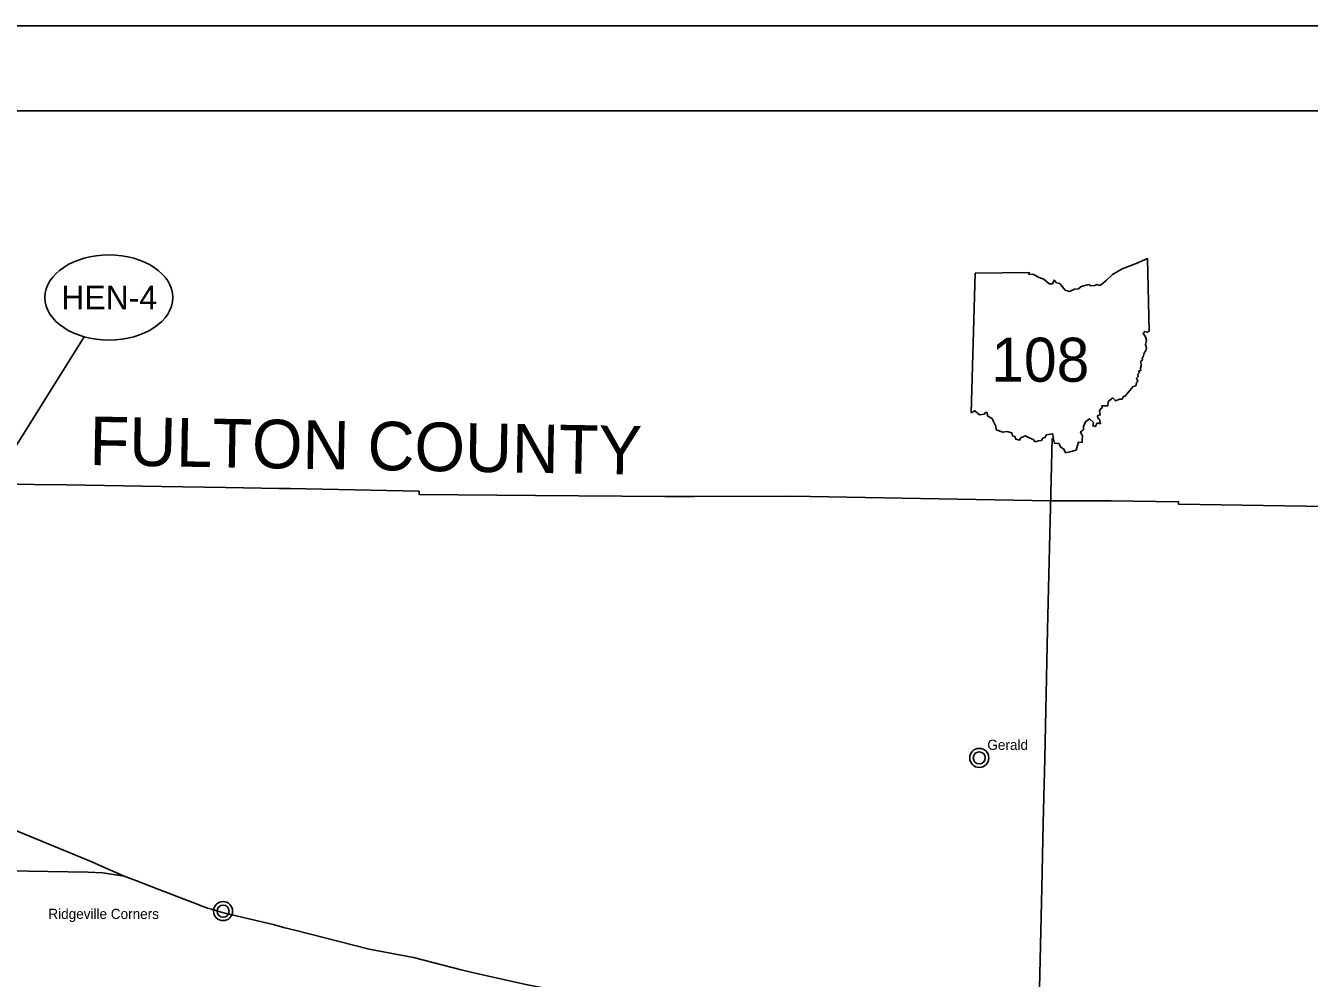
# Model space of a CAD drawing. Extents: x -62 to 810, y 0 to 440.
# Drawn here: x 166.9 to 317.5, y 328.2 to 440 of the extents above; entities that cross this region are included whole.
import ezdxf

# ---------------------------------------------------------------- set-up
doc = ezdxf.new("R2010")
doc.units = 0
for name, color, linetype in [('DV_X_Corp_Line', 7, 'Continuous'), ('GM_X_Adjacent_County_Text', 7, 'Continuous'), ('GM_X_Corporation_Text', 7, 'Continuous'), ('GM_X_County', 7, 'Continuous'), ('GM_X_State_Route', 7, 'Continuous'), ('PV_P_Text', 7, 'Continuous'), ('SH_Border', 7, 'Continuous'), ('SH_Cut_Line', 7, 'Continuous'), ('SH_Data', 7, 'Continuous')]:
    doc.layers.add(name, color=color, linetype=linetype)

msp = doc.modelspace()

# ---------------------------------------------------------------- linework, layer by layer
at = {"layer": 'DV_X_Corp_Line'}
for centre, radius in [((278.8, 354.1), 1.12), ((278.8, 354.1), 0.71), ((190.1, 336.13), 1.12), ((190.1, 336.13), 0.71)]:
    msp.add_circle(centre, radius, dxfattribs=at)
at = {"layer": 'GM_X_County'}
msp.add_lwpolyline([(332.13, 383.45), (317.13, 383.65), (302.18, 383.86), (302.19, 384.14), (294.28, 384.26), (287.17, 384.25), (271.9, 384.53), (256.8, 384.82), (245.35, 384.77), (241.94, 384.75), (241.9, 384.75), (226.74, 384.89), (213.09, 385.02), (213.09, 385.39), (197.99, 385.69), (196.67, 385.72), (190.43, 385.82), (182.87, 385.95), (171.74, 386.13), (167.95, 386.19), (152.77, 386.47)], dxfattribs=at)
at = {"layer": 'GM_X_State_Route'}
for points in [[(285.82, 325.35), (286.13, 338.85), (286.31, 346.44), (286.48, 354.03), (286.82, 369.18), (287.34, 391.58)], [(113.91, 367.23), (136.11, 357.71), (137.35, 357.22), (137.88, 357.01), (139.16, 356.47), (140.26, 355.99), (141.59, 355.46), (142.86, 354.89), (144.45, 354.29), (145.7, 353.79), (147.35, 353.12), (149.16, 352.4), (150.44, 351.87), (151.72, 351.35), (152.35, 351.09), (167.39, 344.92), (174.69, 341.92), (175.91, 341.38), (178.51, 340.22)], [(152.23, 341.07), (159.73, 340.94), (167.27, 340.81), (174.23, 340.71), (176.01, 340.61), (178.51, 340.22)], [(178.51, 340.22), (179.85, 339.71), (179.85, 339.71)], [(179.85, 339.71), (182.38, 338.74), (183.18, 338.43), (185.91, 337.38)], [(185.91, 337.38), (187.18, 336.89), (187.18, 336.89)], [(187.18, 336.89), (187.32, 336.84), (188.27, 336.48), (188.74, 336.35), (189.88, 336.02), (190.48, 335.86), (192.95, 335.27), (193.13, 335.23), (194, 335.02)], [(194, 335.02), (196.12, 334.53), (197.35, 334.17), (198.53, 333.88)], [(198.53, 333.88), (207.22, 331.68), (212.44, 330.67), (218.02, 329.23), (220.04, 328.78), (225.63, 327.52), (227.85, 327.08), (228.67, 326.87), (229.44, 326.61), (229.96, 326.29), (230.45, 325.9), (231.43, 324.88), (234.84, 321.46), (239.2, 317.13), (242.46, 313.89), (243.11, 313.25), (246.06, 310.2), (246.72, 309.53), (248.65, 307.6)]]:
    msp.add_lwpolyline(points, dxfattribs=at)
at = {"layer": 'PV_P_Text'}
msp.add_line((277.87, 394.58), (278.33, 410.95), dxfattribs=at)
msp.add_line((277.87, 394.58), (278.33, 410.95), dxfattribs=at)
for points in [[(278.33, 410.95), (284.68, 411.06), (284.58, 410.86), (285.18, 410.82), (285.82, 410.47), (286.36, 410.25), (287.02, 409.73), (287.41, 409.73), (287.58, 410.16), (287.88, 409.83), (288.24, 409.77), (288.86, 408.99), (289.37, 408.82), (289.98, 409.09), (290.44, 409.13), (290.77, 409.4), (291.65, 409.62), (291.89, 409.49), (292.35, 409.52), (292.58, 409.62), (292.99, 409.53), (293.69, 410.12), (294.42, 410.82), (295.55, 411.49), (297.22, 412.11), (298.55, 412.68), (298.74, 404.18)], [(278.33, 410.95), (284.68, 411.06), (284.58, 410.86), (285.18, 410.82), (285.82, 410.47), (286.36, 410.25), (287.02, 409.73), (287.41, 409.73), (287.58, 410.16), (287.88, 409.83), (288.24, 409.77), (288.86, 408.99), (289.37, 408.82), (289.98, 409.09), (290.44, 409.13), (290.77, 409.4), (291.65, 409.62), (291.89, 409.49), (292.35, 409.52), (292.58, 409.62), (292.99, 409.53), (293.69, 410.12), (294.42, 410.82), (295.55, 411.49), (297.22, 412.11), (298.55, 412.68), (298.74, 404.18)], [(298.74, 404.18), (298.54, 404.06), (298.24, 404.12), (298.03, 403.88), (298.29, 403.48), (298.41, 403.06), (298.3, 402.6), (298.4, 402.21), (298.33, 401.89), (298.14, 401.58), (298.08, 401.27), (297.91, 400.95), (297.93, 400.78), (297.77, 400.63), (297.8, 400.1), (297.72, 399.81), (297.75, 399.55), (297.5, 399.49), (297.55, 399.28), (297.39, 399.11), (297.43, 398.84), (297.25, 398.66), (297.42, 398.3), (297.28, 398.19), (297.16, 397.75), (296.84, 397.67), (296.2, 396.87), (295.97, 396.57), (295.71, 396.5), (295.57, 396.19), (295.26, 396.19), (294.78, 395.98), (294.47, 396.34), (293.93, 395.9), (293.87, 395.39), (293.18, 395.41), (293.21, 395.15), (293.06, 395.07), (292.92, 394.82), (293, 394.36), (292.68, 394.24), (292.72, 393.97), (292.92, 393.81), (293.01, 393.3), (292.67, 393.4), (292.4, 392.97), (292.11, 393.07), (292.2, 393.44), (291.72, 393.88), (291.26, 393.53), (291.02, 392.97), (291.02, 392.59), (290.68, 392.36), (290.9, 391.83), (290.86, 391.46), (290.86, 391.11), (290.44, 391.13), (290.18, 390.19)], [(298.74, 404.18), (298.54, 404.06), (298.24, 404.12), (298.03, 403.88), (298.29, 403.48), (298.41, 403.06), (298.3, 402.6), (298.4, 402.21), (298.33, 401.89), (298.14, 401.58), (298.08, 401.27), (297.91, 400.95), (297.93, 400.78), (297.77, 400.63), (297.8, 400.1), (297.72, 399.81), (297.75, 399.55), (297.5, 399.49), (297.55, 399.28), (297.39, 399.11), (297.43, 398.84), (297.25, 398.66), (297.42, 398.3), (297.28, 398.19), (297.16, 397.75), (296.84, 397.67), (296.2, 396.87), (295.97, 396.57), (295.71, 396.5), (295.57, 396.19), (295.26, 396.19), (294.78, 395.98), (294.47, 396.34), (293.93, 395.9), (293.87, 395.39), (293.18, 395.41), (293.21, 395.15), (293.06, 395.07), (292.92, 394.82), (293, 394.36), (292.68, 394.24), (292.72, 393.97), (292.92, 393.81), (293.01, 393.3), (292.67, 393.4), (292.4, 392.97), (292.11, 393.07), (292.2, 393.44), (291.72, 393.88), (291.26, 393.53), (291.02, 392.97), (291.02, 392.59), (290.68, 392.36), (290.9, 391.83), (290.86, 391.46), (290.86, 391.11), (290.44, 391.13), (290.18, 390.19)], [(290.18, 390.19), (289.44, 390.01), (288.92, 389.9), (288.74, 390.32), (288.37, 390.55), (288.13, 390.98), (287.61, 391.04), (287.48, 391.63), (287.42, 392.11), (286.7, 391.99), (286.5, 391.7), (286.24, 391.62), (286.1, 391.32), (285.75, 391.3), (285.37, 391.16), (285.13, 391.45), (284.51, 391.74), (284.24, 391.89), (283.66, 391.66), (283.54, 391.38), (283.08, 391.5), (282.97, 391.81), (282.69, 391.9), (282.63, 392.23), (282.03, 392.4), (281.58, 392.33), (280.78, 392.59), (280.73, 393.02), (280.46, 393.55), (280.31, 393.91), (279.81, 394.19), (279.7, 394.62), (279.54, 394.61), (279.39, 394.43), (278.83, 394.35), (278.6, 394.53), (278.29, 394.83), (277.87, 394.58)], [(290.18, 390.19), (289.44, 390.01), (288.92, 389.9), (288.74, 390.32), (288.37, 390.55), (288.13, 390.98), (287.61, 391.04), (287.48, 391.63), (287.42, 392.11), (286.7, 391.99), (286.5, 391.7), (286.24, 391.62), (286.1, 391.32), (285.75, 391.3), (285.37, 391.16), (285.13, 391.45), (284.51, 391.74), (284.24, 391.89), (283.66, 391.66), (283.54, 391.38), (283.08, 391.5), (282.97, 391.81), (282.69, 391.9), (282.63, 392.23), (282.03, 392.4), (281.58, 392.33), (280.78, 392.59), (280.73, 393.02), (280.46, 393.55), (280.31, 393.91), (279.81, 394.19), (279.7, 394.62), (279.54, 394.61), (279.39, 394.43), (278.83, 394.35), (278.6, 394.53), (278.29, 394.83), (277.87, 394.58)]]:
    msp.add_lwpolyline(points, dxfattribs=at)
at = {"layer": 'SH_Border'}
msp.add_lwpolyline([(30, 430), (670, 430), (670, 10), (30, 10)], close=True, dxfattribs=at)
at = {"layer": 'SH_Cut_Line'}
msp.add_lwpolyline([(0, 0), (680, 0), (680, 440), (0, 440)], close=True, dxfattribs=at)
at = {"layer": 'SH_Data'}
msp.add_line((173.82, 403.5), (152.57, 369.68), dxfattribs=at)
msp.add_ellipse((176.71, 408.11), major_axis=(7.5, 0), ratio=0.666667, dxfattribs=at)

# ---------------------------------------------------------------- texts
at = {"layer": 'GM_X_Adjacent_County_Text'}
msp.add_text('FULTON COUNTY', height=5.7, rotation=358.9893, dxfattribs=at).set_placement((174.4, 388.46))
at = {"layer": 'GM_X_Corporation_Text'}
for s, height, p in [('Gerald', 1.188, (279.75, 355.04)), ('Ridgeville Corners', 1.1875, (169.61, 335.21))]:
    msp.add_text(s, height=height, rotation=0, dxfattribs=at).set_placement(p)
at = {"layer": 'PV_P_Text'}
msp.add_text('108', height=5.162, dxfattribs=at).set_placement((280.2, 398.23))
at = {"layer": 'SH_Data'}
msp.add_text('HEN-4', height=2.8, dxfattribs=at).set_placement((171.13, 406.71))

doc.saveas('drawing.dxf')
